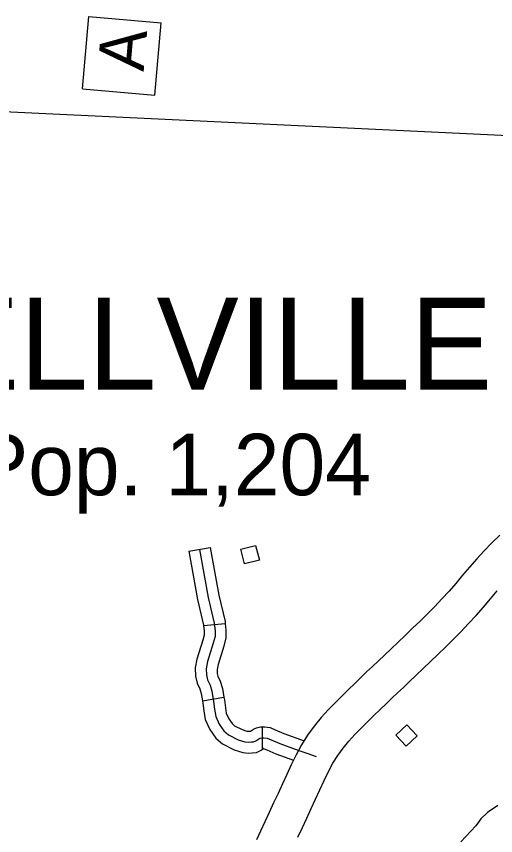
# Model space of a CAD drawing. Extents: x 1370130 to 1380143, y 377636 to 380256.
# Drawn here: x 1377557.8 to 1377650, y 379033.5 to 379191.2 of the extents above; entities that cross this region are included whole.
import ezdxf

# ---------------------------------------------------------------- set-up
doc = ezdxf.new("R2010")
doc.units = 0
for name, color, linetype in [('Level 15', 7, 'Continuous'), ('Level 32', 7, 'Continuous'), ('Level 35', 7, 'Continuous'), ('Level 4', 7, 'Continuous'), ('Level 56', 7, 'Continuous'), ('Level 57', 7, 'Continuous'), ('Level 6', 7, 'Continuous')]:
    doc.layers.add(name, color=color, linetype=linetype)

msp = doc.modelspace()

# ---------------------------------------------------------------- linework, layer by layer
at = {"layer": 'Level 15'}
msp.add_line((1377647.7, 379088.28), (1377647.78, 379088.36), dxfattribs=at)
for points in [[(1377650.8, 379091.36), (1377649.22, 379089.86), (1377647.78, 379088.36)], [(1377647.7, 379088.28), (1377646.34, 379086.78), (1377644.96, 379085.21), (1377643.63, 379083.63), (1377642.32, 379082.08), (1377641.01, 379080.58), (1377639.66, 379079.11), (1377638.29, 379077.66), (1377636.88, 379076.24), (1377635.45, 379074.83), (1377634.01, 379073.43), (1377632.6, 379072.07), (1377631.21, 379070.74), (1377629.87, 379069.47), (1377628.6, 379068.27), (1377627.42, 379067.16), (1377626.28, 379066.09), (1377625.16, 379065.02), (1377624.03, 379063.93), (1377622.87, 379062.81), (1377621.68, 379061.65), (1377620.44, 379060.44), (1377619.14, 379059.15), (1377617.79, 379057.77), (1377616.42, 379056.27), (1377615.06, 379054.62), (1377613.79, 379052.83), (1377612.63, 379050.97), (1377611.58, 379049.04), (1377610.65, 379047.13), (1377609.81, 379045.29), (1377608.97, 379043.49), (1377608.11, 379041.65), (1377607.26, 379039.8), (1377606.42, 379037.96), (1377605.59, 379036.15), (1377604.76, 379034.39), (1377603.93, 379032.68)], [(1377611.94, 379033.2), (1377612.79, 379035.05), (1377613.62, 379036.89), (1377614.46, 379038.71), (1377615.31, 379040.53), (1377616.16, 379042.35), (1377616.99, 379044.15), (1377617.81, 379045.84), (1377618.68, 379047.44), (1377619.61, 379048.94), (1377620.62, 379050.36), (1377621.71, 379051.69), (1377622.88, 379052.97), (1377624.1, 379054.22), (1377625.34, 379055.44), (1377626.57, 379056.64), (1377627.76, 379057.8), (1377628.89, 379058.9), (1377629.99, 379059.96), (1377631.09, 379061), (1377632.22, 379062.06), (1377633.41, 379063.18), (1377634.68, 379064.39), (1377636.04, 379065.68), (1377637.45, 379067.02), (1377638.88, 379068.41), (1377640.34, 379069.83), (1377641.82, 379071.28), (1377643.31, 379072.78), (1377644.79, 379074.34), (1377646.23, 379075.92), (1377647.63, 379077.52), (1377648.97, 379079.11), (1377650.27, 379080.64)]]:
    msp.add_lwpolyline(points, dxfattribs=at)
at = {"layer": 'Level 32'}
for p, q in [((1377590.91, 379088.25), (1377595.03, 379089.01)), ((1377593.78, 379073.94), (1377597.96, 379074.34)), ((1377593.56, 379059.44), (1377597.7, 379060.15)), ((1377605.12, 379050.27), (1377605.12, 379054.47))]:
    msp.add_line(p, q, dxfattribs=at)
for points in [[(1377590.91, 379088.25), (1377592.62, 379078.96), (1377593.76, 379074.06), (1377593.78, 379073.94)], [(1377592.97, 379088.63), (1377594.68, 379079.39), (1377595.84, 379074.4), (1377595.98, 379072.96), (1377595.98, 379071.87), (1377595.64, 379070.57), (1377594.54, 379067.01), (1377594.27, 379065.64), (1377594.34, 379064.48), (1377594.54, 379063.52), (1377595.02, 379062.49), (1377595.36, 379061.33), (1377595.71, 379059.35), (1377595.91, 379057.84), (1377596.12, 379056.47), (1377596.8, 379054.97), (1377597.69, 379053.67), (1377598.58, 379052.92), (1377600.42, 379051.96), (1377601.71, 379051.58), (1377602.39, 379051.51), (1377603, 379051.55), (1377603.41, 379051.58), (1377603.83, 379051.79), (1377604.41, 379052.16), (1377604.68, 379052.3), (1377604.99, 379052.37), (1377605.4, 379052.37), (1377606.01, 379052.27), (1377606.77, 379051.96), (1377608.47, 379051.24), (1377612.13, 379049.91), (1377613.84, 379049.32), (1377615.42, 379048.77)], [(1377595.03, 379089.01), (1377596.74, 379079.82), (1377597.92, 379074.74), (1377597.96, 379074.34)], [(1377597.96, 379074.34), (1377598.08, 379073.06), (1377598.08, 379071.6), (1377597.66, 379069.99), (1377596.58, 379066.49), (1377596.38, 379065.49), (1377596.42, 379064.76), (1377596.55, 379064.19), (1377596.99, 379063.24), (1377597.41, 379061.81), (1377597.7, 379060.15)], [(1377593.78, 379073.94), (1377593.88, 379072.86), (1377593.88, 379072.14), (1377593.62, 379071.14), (1377592.5, 379067.52), (1377592.16, 379065.79), (1377592.25, 379064.19), (1377592.54, 379062.85), (1377593.05, 379061.75), (1377593.31, 379060.85), (1377593.56, 379059.44)], [(1377597.7, 379060.15), (1377597.78, 379059.67), (1377597.99, 379058.14), (1377598.15, 379057.07), (1377598.64, 379056), (1377599.26, 379055.09), (1377599.75, 379054.67), (1377601.21, 379053.92), (1377602.11, 379053.65), (1377602.44, 379053.62), (1377602.82, 379053.64), (1377603.36, 379053.99), (1377603.97, 379054.29), (1377604.76, 379054.47), (1377605.12, 379054.47)], [(1377593.56, 379059.44), (1377593.63, 379059.03), (1377593.83, 379057.54), (1377594.08, 379055.87), (1377594.96, 379053.93), (1377596.11, 379052.25), (1377597.4, 379051.16), (1377599.64, 379050), (1377601.3, 379049.51), (1377602.34, 379049.41), (1377603.15, 379049.45), (1377603.99, 379049.52), (1377604.87, 379049.96), (1377605.34, 379050.27), (1377605.12, 379050.27)], [(1377605.12, 379054.47), (1377605.57, 379054.47), (1377606.59, 379054.3), (1377607.57, 379053.9), (1377609.24, 379053.19), (1377613.13, 379051.78)], [(1377605.12, 379050.27), (1377605.22, 379050.27), (1377605.44, 379050.23), (1377605.96, 379050.02), (1377607.71, 379049.28), (1377611.1, 379048.05)]]:
    msp.add_lwpolyline(points, dxfattribs=at)
at = {"layer": 'Level 35'}
msp.add_lwpolyline([(1377650.43, 379039.34), (1377648.41, 379037.95), (1377647.14, 379036.72), (1377646.19, 379035.38), (1377643.3, 379032.29)], dxfattribs=at)
at = {"layer": 'Level 4'}
msp.add_lwpolyline([(1377687.01, 379166.75), (1377684.84, 379166.69), (1377545.86, 379173.3), (1377543.53, 379173.41), (1377537.66, 379173.5)], dxfattribs=at)
at = {"layer": 'Level 56'}
for points in [[(1377603.8, 379089.36), (1377604.51, 379086.53), (1377601.67, 379085.82), (1377600.96, 379088.65)], [(1377632.9, 379054.85), (1377634.9, 379052.73), (1377632.78, 379050.72), (1377630.78, 379052.84)]]:
    msp.add_lwpolyline(points, close=True, dxfattribs=at)
at = {"layer": 'Level 57'}
for p, q in [((1377570.48, 379177.3), (1377571.7, 379191.25)), ((1377571.7, 379191.25), (1377585.64, 379190.03)), ((1377584.42, 379176.08), (1377585.64, 379190.03)), ((1377570.48, 379177.3), (1377584.42, 379176.08))]:
    msp.add_line(p, q, dxfattribs=at)

# ---------------------------------------------------------------- texts
msp.add_text('A', height=8.87, rotation=85, dxfattribs=at).set_placement((1377582.24, 379180.54))
at = {"layer": 'Level 6'}
for s, height, p in [('YELLVILLE', 17.741, (1377526.69, 379119.35)), ('Pop. 1,204', 11.827, (1377549.48, 379099.05))]:
    msp.add_text(s, height=height, dxfattribs=at).set_placement(p)

doc.saveas('drawing.dxf')
